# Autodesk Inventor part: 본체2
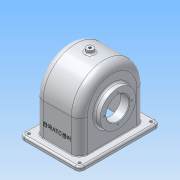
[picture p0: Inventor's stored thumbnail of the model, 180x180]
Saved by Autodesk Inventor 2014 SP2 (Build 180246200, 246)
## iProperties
Created: 2016-01
Part Number: 본체2
Material: 알루미늄 6061
Document SubType Name: Modeling
Designer: User
Mass: 794.903 g
Surface Area: 1006.9 cm^2
Volume: 293.322 cm^3
Density: 2.71 g/cm^3
Appearance: 알루미늄 - 평지
Author: User
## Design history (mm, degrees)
sketch "스케치1"
  geometry: L1 (-57, 0)-(57, 0); L2 (57, 0)-(57, -64); L3 (57, -64)-(-57, -64); L4 (-57, -64)-(-57, 0); C1 r 57 at (0, 0); 2 further points
  constraints: 8 end point, 2 coincident, 2 parallel, 1 centre point, 1 horizontal, 1 midpoint, 1 perpendicular
  dimensions: "d0" = 114 diameter of C1; "d1" = 114 distance of L2.end L3.end; "d2" = 64 distance of L1.end L2.end
extrude "돌출1" new body sketch "스케치1" stored distance "d3" = 77; taper "d4" = 0 deg
feature "쉘1" dims "d7" = 6
sketch "스케치3"
  geometry: L1 (114, 0)-(114, -77) reference; L2 (0, 0)-(114, 0) reference; L3 (0, 0)-(0, -77) reference; L4 (114, -77)-(0, -77) reference; L5 (-13, 13.5)-(127, 13.5); L6 (127, 13.5)-(127, -90.5); L7 (127, -90.5)-(-13, -90.5); L8 (-13, -90.5)-(-13, 13.5); 3 further points
  constraints: 8 end point, 2 midpoint, 2 parallel, 1 horizontal, 1 horizontal alignment, 1 perpendicular, 1 vertical alignment
  dimensions: "d8" = 140 distance of L5.start L5.end; "d9" = 104 distance of L5.end L6.end
extrude "돌출2" join sketch "스케치3" distance "d10" = 7; taper "d11" = 0 deg
fillet "모깎기1" dims "d12" = 14
node "작업 평면1"
sketch "스케치6"
  geometry: C1 r 6 at (0, 0); 1 further point
  constraints: 1 centre point, 1 coincident
  dimensions: "d36" = 12 diameter of C1
extrude "돌출4" join sketch "스케치6" stored distance "d37" = 10; taper "d38" = 0 deg
hole "구멍2" diameter "d41" = 4.459; stored, may be unused: countersink angle "d45" = 90 deg, drill point angle "d47" = 118 deg; dims "d39" = 10, "d40" = 10, "d42" = 6, "d43" = 4, "d44" = 2, "d46" = 63
fillet "모깎기4" dims "d77" = 8
sketch "스케치9"
  geometry: A1 r 8 centre (119, 82.5) between (127, 82.5) and (119, 90.5) reference; A2 r 8 centre (-5, 82.5) between (-5, 90.5) and (-13, 82.5) reference; A3 r 8 centre (-5, -5.5) between (-13, -5.5) and (-5, -13.5) reference; A4 r 8 centre (119, -5.5) between (119, -13.5) and (127, -5.5) reference; 1 further point
hole "구멍5" sketch "스케치9" at (119, 82.5), (-5, 82.5), (119, -5.5), (-5, -5.5) diameter "d78" = 5; stored, may be unused: countersink angle "d82" = 90 deg, drill point angle "d84" = 118 deg; dims "d79" = 7, "d80" = 4, "d81" = 2, "d83" = 9
fillet "모깎기5" dims "d85" = 3
sketch "스케치10"
  geometry: L1 (49, 0)-(49, -57) reference; L2 (0, 0)-(49, 0) reference; L3 (0, -57)-(0, 0) reference; L4 (-1.387, -30.398)-(50.387, -30.398); L5 (50.387, -30.398)-(50.387, -37.602); L6 (50.387, -37.602)-(-1.387, -37.602); L7 (-1.387, -37.602)-(-1.387, -30.398); L8 (0, -34)-(49, -34); L9 (-19.5, -64)-(68.5, -64) reference; L10 (24.5, 0)-(24.5, -54); L11 (-14, 0)-(-14, -57) reference; L12 (68.5, -57)-(-19.5, -57) reference; 4 further points
  constraints: 4 end point, 4 midpoint, 2 point on line, 1 horizontal alignment, 1 perpendicular, 1 vertical alignment, 2 other
  dimensions: "d86" = 30 distance between parallel lines of L9 L8; "d87" = 38.5 distance between parallel lines of L11 L10
feature "엠보싱1" sketch "스케치10" dims "d8" = 140, "d9" = 104, "d88" = 0.5, "d89" = 0
sketch "스케치11"
  geometry: L1 (-51, -64)-(-51, 0) reference; L2 (51, -64)-(-51, -64) reference; L3 (51, 0)-(51, -64) reference; C1 r 20 at (0, -4) reference; A1 r 51 centre (0, 0) between (51, 0) and (-51, 0) reference
extrude "돌출5" cut sketch "스케치11" distance "d90" = 1; taper "d91" = 0 deg
sketch "스케치12"
  geometry: L1 (-51, -64)-(-51, 0) reference; L2 (51, -64)-(-51, -64) reference; L3 (51, 0)-(51, -64) reference; C1 r 38.908 at (0, -4) reference; A1 r 51 centre (0, 0) between (51, 0) and (-51, 0) reference
extrude "돌출6" cut sketch "스케치12" distance "d92" = 1; taper "d93" = 0 deg
sketch "스케치13"
  geometry: L1 (-4, 43.197)-(-4, -48.942); L2 (-64, -33.5)-(-64, 33.5) reference; L3 (16, 35.5)-(30.899, 35.5); L4 (24, 35.5)-(24, 19.5); L5 (24, 19.5)-(16, 19.5); L6 (16, 19.5)-(16, 35.5); L7 (0, 38.5)-(43, 38.5) reference; L8 (24, 19.5)-(39.943, 38.5); L9 (30.899, 35.5)-(33.416, 38.5); L10 (-4, 33.5)-(16, 33.5); L11 (-4, 38.5)-(33.416, 38.5); L12 (-4, 38.5)-(-4, 33.5); 1 further point
  constraints: 20 end point, 6 point on line, 3 parallel, 2 perpendicular, 1 collinear, 1 horizontal, 1 vertical
  dimensions: "d95" = 60 distance between parallel lines of L1 L2; "d96" = 20 distance between parallel lines of L1 L6; "d99" = 50 deg angle of L8 L5; "d100" = 5 distance between parallel lines of L8 L9; "d102" = 5 distance between parallel lines of L10 L11; "d103" = 56 diameter of L4 L1; "d104" = 19 distance between parallel lines of L11 L5; "d105" = 3 distance between parallel lines of L11 L3
revolve "회전3" stored, may be unused: angle "d106" = 90 deg
revolve "회전4" stored, may be unused: angle "d107" = 90 deg
sketch "스케치14"
  geometry: C1 r 20 at (0, -4) reference; C2 r 31 at (0, -4)
  constraints: 1 centre point, 1 coincident
  dimensions: "d108" = 62 diameter of C2
extrude "돌출7" join sketch "스케치14" distance "d109" = 10; taper "d110" = 0 deg
hole "구멍6" diameter "d113" = 40; stored, may be unused: countersink angle "d117" = 90 deg, drill point angle "d119" = 118 deg; dims "d111" = 10, "d112" = 10, "d114" = 6, "d115" = 4, "d116" = 2, "d118" = 8
chamfer "모따기3" distance "d120" = 1; stored, may be unused: second distance "d121" = 2, angle "d122" = 45 deg
fillet "모깎기6" dims "d123" = 3
sketch "스케치15"
  geometry: C1 r 31 at (0, 0) reference; 2 further points
  constraints: 1 vertical alignment
  dimensions: "d124" = 24 distance of C1.centre point (0, 24)
hole "구멍7" sketch "스케치15" at (0, 24) diameter "d125" = 2.459; stored, may be unused: countersink angle "d129" = 90 deg, drill point angle "d131" = 118 deg; dims "d126" = 6, "d127" = 4, "d128" = 2, "d130" = 8
sketch "스케치16"
  geometry: C1 r 21 at (0, 0) reference; 2 further points
  constraints: 1 vertical alignment
  dimensions: "d135" = 28 distance of C1.centre point (0, 28)
hole "구멍8" sketch "스케치16" at (0, 28) diameter "d136" = 2.459; stored, may be unused: countersink angle "d140" = 90 deg, drill point angle "d142" = 118 deg; dims "d137" = 7, "d138" = 4, "d139" = 2, "d141" = 9
fillet "모깎기7" dims "d146" = 9
fillet "모깎기8" dims "d147" = 3
fillet "모깎기9" dims "d148" = 1
node "솔리드1"
pattern_circular "원형 패턴3" dims angle "d133" = 360 deg
pattern_circular "원형 패턴4" dims angle "d144" = 360 deg
other parameters: "d35" = 63
